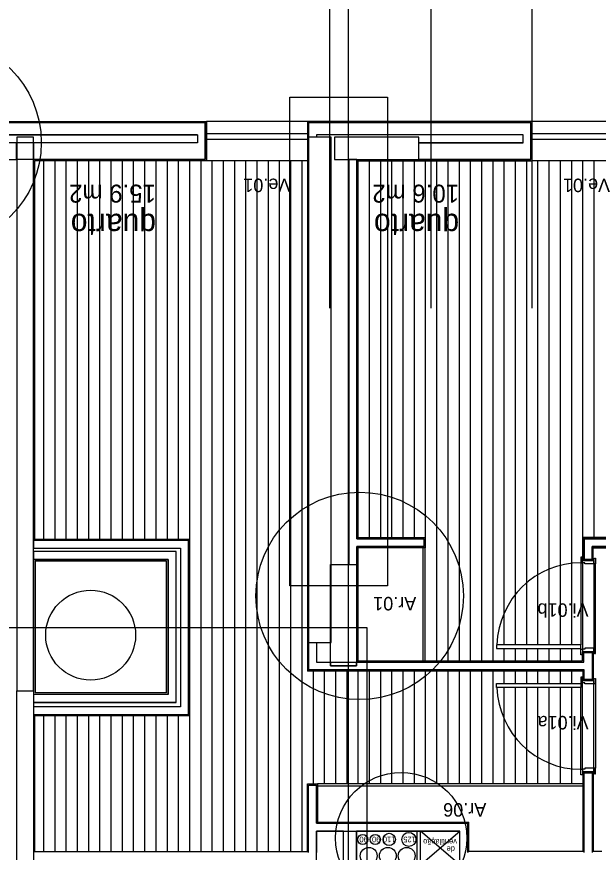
# Model space of a CAD drawing. Extents: x 1278 to 1356, y -253.7 to -224.
# Drawn here: x 1315.61 to 1320.78, y -238.43 to -230.99 of the extents above; entities that cross this region are included whole.
import ezdxf

# ---------------------------------------------------------------- set-up
doc = ezdxf.new("R2010")
doc.units = 0
for name, color, linetype in [('Level 1', 7, 'Continuous'), ('Level 10', 7, 'Continuous'), ('Level 13', 7, 'Continuous'), ('Level 2', 7, 'Continuous'), ('Level 25', 7, 'Continuous'), ('Level 4', 7, 'Continuous'), ('Level 40', 7, 'Continuous'), ('Level 41', 7, 'Continuous'), ('Level 60', 7, 'Continuous'), ('Level 62', 7, 'Continuous'), ('Level 65', 7, 'Continuous'), ('Level 66', 7, 'Continuous'), ('Level 67', 7, 'Continuous'), ('Level 69', 7, 'Continuous'), ('Level 70', 7, 'Continuous'), ('Level 93', 7, 'Continuous')]:
    doc.layers.add(name, color=color, linetype=linetype)

msp = doc.modelspace()

# ---------------------------------------------------------------- linework, layer by layer
at = {"layer": 'Level 1'}
for p, q in [((1315.419, -231.934), (1317.2844, -231.934)), ((1317.2844, -231.934), (1317.2844, -232.264)), ((1318.2044, -231.934), (1318.2044, -232.264)), ((1320.1833, -231.934), (1318.2044, -231.934)), ((1320.1833, -232.264), (1320.1833, -231.934)), ((1317.2144, -232.044), (1317.2144, -232.1143)), ((1320.1133, -232.1143), (1320.1133, -232.044)), ((1318.5633, -232.264), (1318.5633, -235.8713)), ((1318.6333, -232.264), (1320.1833, -232.264)), ((1318.6333, -232.264), (1318.6333, -235.6407)), ((1315.7544, -235.654), (1317.1333, -235.654)), ((1317.1333, -235.654), (1317.1333, -237.209)), ((1318.6333, -235.6407), (1319.2333, -235.6407)), ((1319.2333, -235.6407), (1319.2333, -235.7107)), ((1320.6583, -235.6407), (1320.6583, -235.824)), ((1321.1583, -235.6407), (1320.6583, -235.6407)), ((1315.7544, -235.724), (1317.0633, -235.724)), ((1315.7644, -235.724), (1315.7644, -235.724)), ((1317.0633, -235.724), (1317.0633, -237.139)), ((1319.2333, -235.7107), (1318.6333, -235.7107)), ((1318.6333, -235.7107), (1318.6333, -236.739)), ((1320.7283, -235.824), (1320.7283, -235.7107)), ((1320.7283, -235.7107), (1321.6583, -235.7107)), ((1317.0233, -235.754), (1315.7544, -235.754)), ((1317.0233, -237.099), (1317.0233, -235.754)), ((1316.9533, -235.824), (1315.7544, -235.824)), ((1316.9533, -237.029), (1316.9533, -235.824)), ((1320.6433, -235.824), (1320.7433, -235.824)), ((1320.6433, -236.654), (1320.7433, -236.654)), ((1320.6533, -236.739), (1320.6533, -236.654)), ((1320.7283, -236.654), (1320.7283, -236.894)), ((1318.2744, -236.739), (1320.6533, -236.739)), ((1320.6583, -236.809), (1318.2044, -236.809)), ((1320.6583, -236.894), (1320.6583, -236.809)), ((1320.6433, -236.894), (1320.7433, -236.894)), ((1316.9533, -237.029), (1315.7544, -237.029)), ((1317.0233, -237.099), (1315.7544, -237.099)), ((1317.0633, -237.139), (1315.7544, -237.139)), ((1317.1333, -237.209), (1315.7544, -237.209)), ((1320.6433, -237.724), (1320.7433, -237.724)), ((1320.6583, -238.4357), (1320.6583, -237.724)), ((1320.7283, -237.724), (1320.7283, -238.434)), ((1318.2744, -238.174), (1319.6218, -238.174)), ((1318.2744, -238.244), (1319.551, -238.244)), ((1318.631, -238.544), (1318.631, -238.244)), ((1319.171, -238.544), (1319.171, -238.244)), ((1319.201, -238.544), (1319.201, -238.244)), ((1319.551, -238.499), (1319.551, -238.244))]:
    msp.add_line(p, q, dxfattribs=at)
msp.add_lwpolyline([(1317.2844, -232.264), (1315.6044, -232.264)], dxfattribs=at)
msp.add_circle((1316.2633, -236.499), 0.4, dxfattribs=at)
at = {"layer": 'Level 10'}
for p, q in [((1315.8433, -232.274), (1315.8433, -235.644)), ((1315.9433, -232.274), (1315.9433, -235.644)), ((1316.0433, -232.274), (1316.0433, -235.644)), ((1316.1433, -232.274), (1316.1433, -235.644)), ((1316.2433, -232.274), (1316.2433, -235.644)), ((1316.3433, -232.274), (1316.3433, -235.644)), ((1316.4433, -232.274), (1316.4433, -235.644)), ((1316.5433, -232.274), (1316.5433, -235.644)), ((1316.6433, -232.274), (1316.6433, -235.644)), ((1316.7433, -232.274), (1316.7433, -235.644)), ((1316.8433, -232.274), (1316.8433, -235.644)), ((1316.9433, -232.274), (1316.9433, -235.644)), ((1317.0433, -232.274), (1317.0433, -235.644)), ((1317.1433, -232.274), (1317.1433, -235.644)), ((1317.2433, -232.274), (1317.2433, -238.4257)), ((1317.3433, -232.274), (1317.3433, -238.4257)), ((1317.4433, -232.274), (1317.4433, -238.4257)), ((1317.5433, -232.274), (1317.5433, -238.4257)), ((1317.6433, -232.274), (1317.6433, -238.4257)), ((1317.7433, -232.274), (1317.7433, -238.4257)), ((1317.8433, -232.274), (1317.8433, -238.4257)), ((1317.9433, -232.274), (1317.9433, -238.4257)), ((1318.0433, -232.274), (1318.0433, -238.4257)), ((1318.1433, -232.274), (1318.1433, -238.4257)), ((1318.7433, -232.274), (1318.7433, -235.6307)), ((1318.8433, -232.274), (1318.8433, -235.6307)), ((1318.9433, -232.274), (1318.9433, -235.6307)), ((1319.0433, -232.274), (1319.0433, -235.6307)), ((1319.1433, -232.274), (1319.1433, -235.6307)), ((1319.2433, -232.274), (1319.2433, -235.6307)), ((1319.3433, -232.274), (1319.3433, -236.729)), ((1319.4433, -232.274), (1319.4433, -236.729)), ((1319.5433, -232.274), (1319.5433, -236.729)), ((1319.6433, -232.274), (1319.6433, -236.729)), ((1319.7433, -232.274), (1319.7433, -236.729)), ((1319.8433, -232.274), (1319.8433, -236.729)), ((1319.9433, -232.274), (1319.9433, -236.584)), ((1320.0433, -232.274), (1320.0433, -236.584)), ((1320.1433, -232.274), (1320.1433, -236.584)), ((1320.2433, -232.274), (1320.2433, -236.584)), ((1320.3433, -232.274), (1320.3433, -236.584)), ((1320.4433, -232.274), (1320.4433, -236.584)), ((1320.5433, -232.274), (1320.5433, -236.584)), ((1320.6433, -232.274), (1320.6433, -235.829)), ((1320.7433, -232.274), (1320.7433, -235.6307)), ((1320.6433, -235.854), (1320.6433, -236.624)), ((1320.7433, -235.864), (1320.7433, -236.614)), ((1319.9433, -236.619), (1319.9433, -236.729)), ((1320.0433, -236.619), (1320.0433, -236.729)), ((1320.1433, -236.619), (1320.1433, -236.729)), ((1320.2433, -236.619), (1320.2433, -236.729)), ((1320.3433, -236.619), (1320.3433, -236.729)), ((1320.4433, -236.619), (1320.4433, -236.729)), ((1320.5433, -236.619), (1320.5433, -236.729)), ((1318.2433, -236.819), (1318.2433, -237.824)), ((1318.3433, -236.819), (1318.3433, -237.824)), ((1318.4433, -236.819), (1318.4433, -237.824)), ((1318.5433, -236.819), (1318.5433, -237.824)), ((1318.6433, -236.819), (1318.6433, -237.824)), ((1318.7433, -236.819), (1318.7433, -237.824)), ((1318.8433, -236.819), (1318.8433, -237.824)), ((1318.9433, -236.819), (1318.9433, -237.824)), ((1319.0433, -236.819), (1319.0433, -237.824)), ((1319.1433, -236.819), (1319.1433, -237.824)), ((1319.2433, -236.819), (1319.2433, -237.824)), ((1319.3433, -236.819), (1319.3433, -237.824)), ((1319.4433, -236.819), (1319.4433, -237.824)), ((1319.5433, -236.824), (1319.5433, -237.824)), ((1319.6433, -236.824), (1319.6433, -237.824)), ((1319.7433, -236.824), (1319.7433, -237.824)), ((1319.8433, -236.824), (1319.8433, -237.824)), ((1319.9433, -236.824), (1319.9433, -236.929)), ((1320.0433, -236.824), (1320.0433, -236.929)), ((1320.1433, -236.824), (1320.1433, -236.929)), ((1320.2433, -236.824), (1320.2433, -236.929)), ((1320.3433, -236.824), (1320.3433, -236.929)), ((1320.4433, -236.824), (1320.4433, -236.929)), ((1320.5433, -236.824), (1320.5433, -236.929)), ((1320.6433, -237.694), (1320.6433, -236.924)), ((1320.7433, -237.684), (1320.7433, -236.934)), ((1319.9433, -236.964), (1319.9433, -237.824)), ((1320.0433, -236.964), (1320.0433, -237.824)), ((1320.1433, -236.964), (1320.1433, -237.824)), ((1320.2433, -236.964), (1320.2433, -237.824)), ((1320.3433, -236.964), (1320.3433, -237.824)), ((1320.4433, -236.964), (1320.4433, -237.824)), ((1320.5433, -236.964), (1320.5433, -237.824)), ((1315.8433, -237.219), (1315.8433, -238.4257)), ((1315.9433, -237.219), (1315.9433, -238.4257)), ((1316.0433, -237.219), (1316.0433, -238.4257)), ((1316.1433, -237.219), (1316.1433, -238.4257)), ((1316.2433, -237.219), (1316.2433, -238.4257)), ((1316.3433, -237.219), (1316.3433, -238.4257)), ((1316.4433, -237.219), (1316.4433, -238.4257)), ((1316.5433, -237.219), (1316.5433, -238.4257)), ((1316.6433, -237.219), (1316.6433, -238.4257)), ((1316.7433, -237.219), (1316.7433, -238.4257)), ((1316.8433, -237.219), (1316.8433, -238.4257)), ((1316.9433, -237.219), (1316.9433, -238.4257)), ((1317.0433, -237.219), (1317.0433, -238.4257)), ((1317.1433, -237.219), (1317.1433, -238.4257))]:
    msp.add_line(p, q, dxfattribs=at)
at = {"layer": 'Level 13'}
for p, q in [((1319.2233, -236.729), (1319.2233, -235.7207)), ((1319.2433, -236.729), (1319.2433, -235.7207)), ((1320.6283, -235.804), (1320.6283, -235.854)), ((1320.6383, -235.804), (1320.6283, -235.804)), ((1320.6383, -235.809), (1320.6383, -235.804)), ((1320.6433, -235.809), (1320.6383, -235.809)), ((1320.6433, -235.854), (1320.6433, -235.809)), ((1320.7433, -235.864), (1320.7433, -235.819)), ((1320.7433, -235.819), (1320.7483, -235.819)), ((1320.7483, -235.819), (1320.7483, -235.814)), ((1320.7483, -235.814), (1320.7583, -235.814)), ((1320.7583, -235.814), (1320.7583, -235.864)), ((1320.6283, -235.854), (1320.6433, -235.854)), ((1320.6433, -235.834), (1320.7433, -235.834)), ((1320.6433, -235.854), (1320.6433, -235.834)), ((1320.6633, -235.854), (1320.6433, -235.854)), ((1320.6633, -235.864), (1320.6633, -235.854)), ((1320.7433, -235.864), (1320.6633, -235.864)), ((1320.7433, -235.834), (1320.7433, -235.864)), ((1320.7583, -235.864), (1320.7433, -235.864)), ((1320.6283, -236.584), (1319.8783, -236.584)), ((1319.8783, -236.584), (1319.8783, -236.619)), ((1319.8783, -236.619), (1320.6283, -236.619)), ((1320.6283, -236.619), (1320.6283, -236.584)), ((1320.6283, -236.674), (1320.6283, -236.624)), ((1320.6283, -236.624), (1320.6433, -236.624)), ((1320.6633, -236.624), (1320.6433, -236.624)), ((1320.6433, -236.624), (1320.6433, -236.644)), ((1320.6433, -236.624), (1320.6433, -236.669)), ((1320.7433, -236.614), (1320.6633, -236.614)), ((1320.6633, -236.614), (1320.6633, -236.624)), ((1320.7433, -236.644), (1320.7433, -236.614)), ((1320.7583, -236.614), (1320.7433, -236.614)), ((1320.7433, -236.614), (1320.7433, -236.659)), ((1320.7583, -236.664), (1320.7583, -236.614)), ((1320.6383, -236.674), (1320.6283, -236.674)), ((1320.6433, -236.669), (1320.6383, -236.669)), ((1320.6383, -236.669), (1320.6383, -236.674)), ((1320.6433, -236.644), (1320.7433, -236.644)), ((1320.7433, -236.659), (1320.7483, -236.659)), ((1320.7483, -236.659), (1320.7483, -236.664)), ((1320.7483, -236.664), (1320.7583, -236.664)), ((1319.8783, -236.929), (1320.6283, -236.929)), ((1319.8783, -236.964), (1319.8783, -236.929)), ((1320.6283, -236.874), (1320.6283, -236.924)), ((1320.6383, -236.874), (1320.6283, -236.874)), ((1320.6283, -236.924), (1320.6433, -236.924)), ((1320.6283, -236.929), (1320.6283, -236.964)), ((1320.6383, -236.879), (1320.6383, -236.874)), ((1320.6433, -236.879), (1320.6383, -236.879)), ((1320.6433, -236.924), (1320.6433, -236.879)), ((1320.6433, -236.904), (1320.7433, -236.904)), ((1320.6433, -236.924), (1320.6433, -236.904)), ((1320.6633, -236.924), (1320.6433, -236.924)), ((1320.6633, -236.934), (1320.6633, -236.924)), ((1320.7433, -236.934), (1320.6633, -236.934)), ((1320.7433, -236.934), (1320.7433, -236.889)), ((1320.7433, -236.889), (1320.7483, -236.889)), ((1320.7433, -236.904), (1320.7433, -236.934)), ((1320.7583, -236.934), (1320.7433, -236.934)), ((1320.7483, -236.889), (1320.7483, -236.884)), ((1320.7483, -236.884), (1320.7583, -236.884)), ((1320.7583, -236.884), (1320.7583, -236.934)), ((1320.6283, -236.964), (1319.8783, -236.964)), ((1320.6283, -237.744), (1320.6283, -237.694)), ((1320.6283, -237.694), (1320.6433, -237.694)), ((1320.6383, -237.744), (1320.6283, -237.744)), ((1320.6433, -237.739), (1320.6383, -237.739)), ((1320.6383, -237.739), (1320.6383, -237.744)), ((1320.6433, -237.694), (1320.6433, -237.739)), ((1320.6633, -237.694), (1320.6433, -237.694)), ((1320.6433, -237.694), (1320.6433, -237.714)), ((1320.6433, -237.714), (1320.7433, -237.714)), ((1320.7433, -237.684), (1320.6633, -237.684)), ((1320.6633, -237.684), (1320.6633, -237.694)), ((1320.7583, -237.684), (1320.7433, -237.684)), ((1320.7433, -237.684), (1320.7433, -237.729)), ((1320.7433, -237.714), (1320.7433, -237.684)), ((1320.7433, -237.729), (1320.7483, -237.729)), ((1320.7483, -237.729), (1320.7483, -237.734)), ((1320.7483, -237.734), (1320.7583, -237.734)), ((1320.7583, -237.734), (1320.7583, -237.684)), ((1320.6483, -237.824), (1318.2843, -237.824)), ((1320.6483, -237.844), (1318.2843, -237.844))]:
    msp.add_line(p, q, dxfattribs=at)
at = {"layer": 'Level 2'}
for p, q in [((1318.1944, -231.924), (1317.2944, -231.924)), ((1321.0933, -231.924), (1320.1933, -231.924)), ((1318.1944, -232.034), (1317.2944, -232.034)), ((1318.1944, -232.084), (1317.2944, -232.084)), ((1321.0933, -232.034), (1320.1933, -232.034)), ((1321.0933, -232.084), (1320.1933, -232.084)), ((1318.1944, -232.274), (1317.2944, -232.274)), ((1321.0933, -232.274), (1320.1933, -232.274))]:
    msp.add_line(p, q, dxfattribs=at)
at = {"layer": 'Level 25'}
msp.add_lwpolyline([(1319.1843, -232.264), (1319.1843, -232.0639), (1318.4343, -232.0639), (1318.4343, -232.264)], close=True, dxfattribs=at)
at = {"layer": 'Level 4'}
for p, q in [((1320.6283, -235.854), (1320.6283, -236.584)), ((1320.7583, -236.614), (1320.7583, -235.864)), ((1320.7583, -236.934), (1320.7583, -237.684)), ((1320.6283, -237.694), (1320.6283, -236.964))]:
    msp.add_line(p, q, dxfattribs=at)
for centre, major_axis, start_param, end_param in [((1320.6283, -236.6172), (0, -0.7632), 3.141593, 4.668897), ((1320.6283, -236.9308), (0, 0.7632), 1.614288, 3.141593)]:
    msp.add_ellipse(centre, major_axis=major_axis, ratio=0.982661, start_param=start_param, end_param=end_param, dxfattribs=at)
at = {"layer": 'Level 41'}
for p, q in [((1319.551, -238.544), (1319.201, -238.244)), ((1319.201, -238.544), (1319.551, -238.244))]:
    msp.add_line(p, q, dxfattribs=at)
for centre, radius in [((1318.6858, -238.3185), 0.045), ((1318.7978, -238.3185), 0.045), ((1318.9218, -238.3185), 0.055), ((1319.0967, -238.3185), 0.0625), ((1318.7393, -238.4644), 0.075), ((1318.9095, -238.4644), 0.075), ((1319.0775, -238.4644), 0.075)]:
    msp.add_circle(centre, radius, dxfattribs=at)
at = {"layer": 'Level 62'}
for p, q in [((1319.2299, -232.274), (1319.2207, -232.274)), ((1318.6433, -232.8454), (1318.6433, -233.4014))]:
    msp.add_line(p, q, dxfattribs=at)
at = {"layer": 'Level 65'}
for p, q in [((1315.409, -231.924), (1317.2944, -231.924)), ((1317.2944, -231.924), (1317.2944, -232.274)), ((1320.1933, -231.924), (1318.1944, -231.924)), ((1318.1944, -231.924), (1318.1944, -232.274)), ((1320.1933, -232.274), (1320.1933, -231.924)), ((1318.1944, -232.0639), (1318.1944, -236.819)), ((1315.7644, -232.274), (1315.7644, -235.644)), ((1318.6433, -232.274), (1318.6433, -235.6307)), ((1318.6433, -232.274), (1320.1933, -232.274)), ((1315.7644, -235.644), (1317.1433, -235.644)), ((1317.1433, -235.644), (1317.1433, -237.219)), ((1318.6433, -235.6307), (1319.2433, -235.6307)), ((1319.2433, -235.6307), (1319.2433, -235.7207)), ((1321.1483, -235.6307), (1320.6483, -235.6307)), ((1320.6483, -235.6307), (1320.6483, -235.824)), ((1319.2433, -235.7207), (1318.6433, -235.7207)), ((1318.6433, -235.7207), (1318.6433, -236.729)), ((1320.7383, -235.824), (1320.7383, -235.7207)), ((1320.7383, -235.7207), (1321.6483, -235.7207)), ((1316.9383, -235.839), (1315.7694, -235.839)), ((1315.7694, -235.839), (1315.7694, -237.014)), ((1316.9383, -237.014), (1316.9383, -235.839)), ((1320.6433, -236.729), (1320.6433, -236.654)), ((1320.7383, -236.654), (1320.7383, -236.894)), ((1318.6433, -236.729), (1320.6433, -236.729)), ((1320.6483, -236.819), (1318.1944, -236.819)), ((1320.6483, -236.894), (1320.6483, -236.819)), ((1316.9383, -237.014), (1315.7694, -237.014)), ((1317.1433, -237.219), (1315.7644, -237.219)), ((1315.7644, -237.219), (1315.7644, -238.424)), ((1320.6483, -238.4257), (1320.6483, -237.724)), ((1320.7383, -237.724), (1320.7383, -238.4257)), ((1318.1944, -237.824), (1318.2843, -237.824)), ((1318.2843, -237.824), (1318.2843, -238.164)), ((1318.2843, -238.164), (1319.6318, -238.164)), ((1319.6318, -238.4257), (1319.6318, -238.164)), ((1315.7644, -238.4257), (1318.1944, -238.4257)), ((1320.6483, -238.4257), (1319.6318, -238.4257)), ((1320.816, -238.4257), (1320.7383, -238.4257))]:
    msp.add_line(p, q, dxfattribs=at)
for points in [[(1317.2944, -232.274), (1315.7644, -232.274)], [(1318.1944, -238.4257), (1318.1944, -237.824)]]:
    msp.add_lwpolyline(points, dxfattribs=at)
at = {"layer": 'Level 66'}
for p, q in [((1317.2144, -232.044), (1315.489, -232.044)), ((1318.2044, -232.0639), (1318.2044, -236.809)), ((1320.1133, -232.044), (1318.2744, -232.044)), ((1318.2744, -232.044), (1318.2744, -232.0639)), ((1317.2144, -232.1143), (1315.489, -232.1143)), ((1320.1133, -232.1143), (1319.1843, -232.1143)), ((1315.7544, -235.824), (1315.7544, -242.1713)), ((1318.2744, -236.5639), (1318.2744, -236.739)), ((1318.2044, -238.4357), (1318.2044, -237.834)), ((1318.2744, -237.834), (1318.2044, -237.834)), ((1318.2744, -238.174), (1318.2744, -237.834)), ((1319.6218, -238.4357), (1319.6218, -238.174)), ((1318.2744, -238.5057), (1318.2744, -238.244)), ((1318.5133, -238.544), (1318.5133, -238.244))]:
    msp.add_line(p, q, dxfattribs=at)
for points in [[(1315.7544, -232.064), (1315.6056, -232.064), (1315.6056, -236.994), (1315.7544, -236.994)], [(1318.2044, -236.5639), (1318.4044, -236.5639), (1318.4044, -232.0639), (1318.2044, -232.0639)], [(1318.2044, -236.5639), (1318.4044, -236.5639), (1318.4044, -232.0639), (1318.2044, -232.0639)], [(1318.4343, -232.264), (1319.1843, -232.264), (1319.1843, -232.0639), (1318.4343, -232.0639)], [(1318.4003, -235.8713), (1318.6303, -235.8713), (1318.6303, -236.7713), (1318.4003, -236.7713)]]:
    msp.add_lwpolyline(points, close=True, dxfattribs=at)
at = {"layer": 'Level 67'}
for points in [[(1315.6044, -232.264), (1315.6044, -232.1143), (1315.489, -232.1143), (1315.489, -232.044), (1317.2144, -232.044), (1317.2144, -232.1143), (1315.7544, -232.1143), (1315.7544, -232.264), (1317.2844, -232.264), (1317.2844, -231.934), (1315.419, -231.934), (1315.419, -232.264)], [(1318.2044, -231.934), (1320.1833, -231.934), (1320.1833, -232.264), (1319.1843, -232.264), (1319.1843, -232.1143), (1320.1133, -232.1143), (1320.1133, -232.044), (1318.2744, -232.044), (1318.2744, -232.0639), (1318.2044, -232.0639)], [(1318.5633, -235.8713), (1318.6333, -235.8713), (1318.6333, -235.7107), (1319.2333, -235.7107), (1319.2333, -235.6407), (1318.6333, -235.6407), (1318.6333, -232.264), (1318.5633, -232.264)], [(1321.6583, -235.824), (1321.6583, -235.7107), (1320.7283, -235.7107), (1320.7283, -235.824), (1320.6583, -235.824), (1320.6583, -235.6407), (1321.1583, -235.6407), (1321.1583, -232.264), (1321.2283, -232.264), (1321.2283, -235.6407), (1321.7283, -235.6407), (1321.7283, -235.824)], [(1315.7544, -237.209), (1317.1333, -237.209), (1317.1333, -235.654), (1315.7544, -235.654), (1315.7544, -235.724), (1317.0633, -235.724), (1317.0633, -237.139), (1315.7544, -237.139)], [(1315.7544, -237.099), (1317.0233, -237.099), (1317.0233, -235.754), (1315.7544, -235.754), (1315.7544, -235.824), (1316.9533, -235.824), (1316.9533, -237.029), (1315.7544, -237.029)], [(1320.7283, -236.894), (1320.6583, -236.894), (1320.6583, -236.809), (1318.2044, -236.809), (1318.2044, -236.5639), (1318.2744, -236.5639), (1318.2744, -236.739), (1318.4003, -236.739), (1318.4003, -236.7713), (1318.6303, -236.7713), (1318.6303, -236.739), (1320.6533, -236.739), (1320.6533, -236.654), (1320.7283, -236.654)], [(1315.7544, -236.994), (1315.7544, -242.1713), (1315.5134, -242.1713), (1315.5134, -242.1013), (1315.6044, -242.1013), (1315.6056, -236.994)]]:
    msp.add_lwpolyline(points, close=True, dxfattribs=at)
for points in [[(1320.6583, -238.4357), (1320.6583, -237.724), (1320.7283, -237.724), (1320.7283, -238.4357)], [(1318.2044, -238.4357), (1318.2044, -237.834), (1318.2744, -237.834), (1318.2744, -238.174), (1318.5133, -238.174), (1319.6218, -238.174), (1319.6218, -238.4357)], [(1318.5133, -238.544), (1318.5133, -238.244), (1318.2744, -238.244), (1318.2744, -238.4357)], [(1319.551, -238.5057), (1319.551, -238.244), (1318.631, -238.244), (1318.631, -238.544)]]:
    msp.add_lwpolyline(points, dxfattribs=at)
at = {"layer": 'Level 69'}
for points in [[(1318.9067, -236.0598), (1318.0365, -236.0598), (1318.0365, -231.7084), (1318.9067, -231.7084)], [(1318.7233, -238.934), (1315.3724, -238.934), (1315.3724, -236.4315), (1318.7233, -236.4315)]]:
    msp.add_lwpolyline(points, close=True, dxfattribs=at)
for centre, radius in [((1314.9002, -232.1122), 0.9238), ((1318.6587, -236.1495), 0.9238), ((1319.0278, -238.3059), 0.5842)]:
    msp.add_circle(centre, radius, dxfattribs=at)
at = {"layer": 'Level 70'}
msp.add_line((1318.5594, -250.7923), (1318.5594, -229.6198), dxfattribs=at)
at = {"layer": 'Level 93'}
for p, q in [((1318.394, -233.587), (1318.394, -228.3936)), ((1319.294, -233.587), (1319.294, -228.3936)), ((1320.194, -233.587), (1320.194, -228.3936))]:
    msp.add_line(p, q, dxfattribs=at)

# ---------------------------------------------------------------- texts
at = {"layer": 'Level 40'}
for s, rotation, p in [('Ve.01', 180.00001, (1318.0416, -232.4333)), ('Ve.01', 180.00001, (1320.8881, -232.4333)), ('Ar.01', 179.99999, (1319.1626, -236.1586)), ('Vi.01b', 180.00001, (1320.6971, -236.2158)), ('Vi.01a', 180.00001, (1320.6971, -237.2185)), ('Ar.06', 179.99999, (1319.786, -237.9953))]:
    msp.add_text(s, height=0.12, rotation=rotation, dxfattribs=at).set_placement(p)
at = {"layer": 'Level 41'}
for s, p in [('90', (1318.7308, -238.2935)), ('90', (1318.8428, -238.2935)), ('110', (1318.9768, -238.2935)), ('125', (1319.1592, -238.2935)), ('ventilação ', (1319.525, -238.3155)), (' de ', (1319.525, -238.3799))]:
    msp.add_text(s, height=0.05, rotation=180, dxfattribs=at).set_placement(p)
at = {"layer": 'Level 60'}
for s, height, p in [('15.9 m2', 0.16, (1316.8448, -232.487)), ('10.6 m2', 0.16, (1319.5442, -232.487)), ('quarto', 0.2, (1316.8448, -232.7464)), ('quarto', 0.2, (1319.5442, -232.7464))]:
    msp.add_text(s, height=height, rotation=180, dxfattribs=at).set_placement(p)

doc.saveas('drawing.dxf')
